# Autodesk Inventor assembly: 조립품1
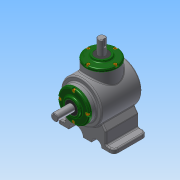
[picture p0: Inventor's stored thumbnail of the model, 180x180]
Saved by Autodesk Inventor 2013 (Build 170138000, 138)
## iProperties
Created: 2018-08
Part Number: 조립품1
Document SubType Name: Assembly
Designer: Administrator
Author: Administrator
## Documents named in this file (14)
- C:\Users\Administrator\Desktop\480808V1026\조립품1.iam
- C:\Users\Administrator\Desktop\480808V1026\본체.ipt
- C:\Users\Administrator\Desktop\480808V1026\메인 축.ipt
- 메인 축.ipt
- C:\Users\Administrator\Desktop\480808V1026\베어링 6203.ipt
- C:\Users\Administrator\Desktop\480808V1026\키 5x5.ipt
- C:\Users\Administrator\Desktop\480808V1026\메인 베벨기어.ipt
- C:\Users\Administrator\Desktop\480808V1026\커버.ipt
- C:\Users\Administrator\Desktop\480808V1026\오일실 17 32 8.ipt
- C:\Users\Administrator\Desktop\480808V1026\볼트 M4.ipt
- C:\Users\Administrator\Desktop\480808V1026\서브 축.ipt
- 서브 축.ipt
- C:\Users\Administrator\Desktop\480808V1026\키 4x4.ipt
- C:\Users\Administrator\Desktop\480808V1026\서브 베벨기어.ipt
